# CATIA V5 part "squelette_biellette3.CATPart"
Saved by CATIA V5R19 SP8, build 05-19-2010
Part number: squelette_biellette3
Publications: "Plan.1", "Point.1", "Droite.1", "Point.8"
Bounding box of the stored display mesh (mm): x 2.851 to 43.851, y 251.964 to 343.821, z 64.119 to 88.354
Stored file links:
  G:\EU_thinkMotion\CFAO_2010\MMS_groupe3\MMS_groupe3\A reprendre\amenand\amenand\squelette_biellette3.CATPart
  F:\thinkmotion CFAO v12.1\essuie_glace.CATProduct
  G:\EU_thinkMotion\CFAO_2010\MMS_groupe3\MMS_groupe3\A reprendre\amenand\amenand\squelette_pignon.CATPart
  G:\EU_thinkMotion\CFAO_2010\MMS_groupe3\MMS_groupe3\A reprendre\amenand\amenand\squelette_coulisseau.CATPart
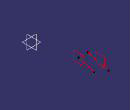
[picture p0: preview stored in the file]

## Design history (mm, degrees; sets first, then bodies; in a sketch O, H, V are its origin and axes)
Set1
  Plane1: linked copy from another document
  Point1: linked copy from another document
  Line1: linked copy from another document
  Point2: linked copy from another document
Set2 "set géométrique.11"
  Plane2: type Offset, RefPlane Plane1, Offset 41, reversed
  Point3: type OnPlane, Support Plane2, RefPoint Point1, H 0, V 0, Direction (0, 1, 0)
  Line2: type PtDir, RefPoint Point3, Direction Line1, Support Plane2, Start 0, End 95
  Point4: type OnCurve, Support Line2, RefPoint Point2, Length 0
  Point5: type OnCurve, Support Line2, RefPoint Point4, Length 63
Body1 (main body)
